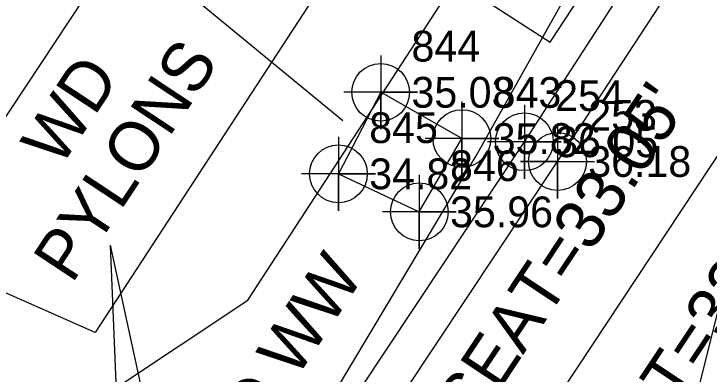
# Model space of a CAD drawing. Extents: x 2603627 to 2605187, y 896619 to 899063.
# Drawn here: x 2604536.5 to 2604593, y 898218.4 to 898247.7 of the extents above; entities that cross this region are included whole.
import ezdxf

# ---------------------------------------------------------------- set-up
doc = ezdxf.new("R2010")
doc.units = 0
for name, color, linetype in [('Exist Guardrail', 7, 'Continuous'), ('Exist Horizontal Alignment', 7, 'Continuous'), ('Exist Other Culture Area Outline', 7, 'Continuous'), ('Exist Other Culture Area Outline Cogo Elevation', 7, 'Continuous'), ('Exist Other Culture Area Outline Cogo Number', 7, 'Continuous'), ('Exist Other Culture Area Outline Cogo Point CELL', 7, 'Continuous'), ('Exist Other Culture Area Outline Leader', 7, 'Continuous'), ('Exist Other Culture Located Object Leader', 7, 'Continuous'), ('Exist Other Culture Located Object Text', 7, 'Continuous'), ('Exist Property Tie Line', 7, 'Continuous'), ('Exist Right of Way Line', 7, 'Continuous'), ('Exist Roads EOP', 7, 'Continuous'), ('Exist Roads EOP Cogo Elevation', 7, 'Continuous'), ('Exist Roads EOP Cogo Number', 7, 'Continuous'), ('Exist Roads EOP Cogo Point CELL', 7, 'Continuous'), ('Exist Roads EOT', 7, 'Continuous'), ('Exist Roads EOT Cogo Elevation', 7, 'Continuous'), ('Exist Roads EOT Cogo Number', 7, 'Continuous'), ('Exist Roads EOT Cogo Point CELL', 7, 'Continuous'), ('Exist Structure Major Bridge Seat Top Elevation', 7, 'Continuous'), ('Exist Structure Major Bridge WW Text', 7, 'Continuous'), ('Exist Utilities Telephone UG Cable SUE LOS C', 7, 'Continuous'), ('Exist Utilities Telephone UG FO SUE LOS C', 7, 'Continuous'), ('Exist Vegetation Woods Line', 7, 'Continuous')]:
    doc.layers.add(name, color=color, linetype=linetype)

# ---------------------------------------------------------------- blocks, each defined once
blk = doc.blocks.new('EXIST ROADS EOT COGO POINT')
at = {"layer": 'Exist Roads EOT Cogo Point CELL'}
blk.add_lwpolyline([(0, 0.06), (0, -0.06), (0, 0), (-0.06, 0), (0.06, 0)], dxfattribs=at)
blk.add_circle((0, 0), 0.0469, dxfattribs=at)
blk = doc.blocks.new('EXIST ROADS EOP COGO POINT')
at = {"layer": 'Exist Roads EOP Cogo Point CELL'}
blk.add_lwpolyline([(0, 0.06), (0, -0.06), (0, 0), (0.06, 0), (-0.06, 0)], dxfattribs=at)
blk.add_circle((0, 0), 0.0469, dxfattribs=at)
blk = doc.blocks.new('EXIST OTHER CULTURE AREA OUTLINE COGO POINT')
at = {"layer": 'Exist Other Culture Area Outline Cogo Point CELL'}
blk.add_lwpolyline([(0, 0.06), (0, -0.06), (0, 0), (0.06, 0), (-0.06, 0)], dxfattribs=at)
blk.add_circle((0, 0), 0.0469, dxfattribs=at)

msp = doc.modelspace()

# ---------------------------------------------------------------- linework, layer by layer
at = {"layer": 'Exist Guardrail'}
msp.add_lwpolyline([(2604549.447, 898197.005), (2604551.688, 898200.424), (2604561.034, 898214.376), (2604574.047, 898236.144), (2604583.438, 898252.897), (2604603.34, 898290.06), (2604614.453, 898307.438), (2604661.781, 898380.221)], dxfattribs=at)
at = {"layer": 'Exist Horizontal Alignment'}
msp.add_line((2604537.349, 898151.011), (2604647.762, 898317.915), dxfattribs=at)
at = {"layer": 'Exist Other Culture Area Outline'}
msp.add_lwpolyline([(2604572.88, 898237.533), (2604566.28, 898241.293), (2604562.846, 898234.669), (2604569.416, 898231.58), (2604572.88, 898237.533)], dxfattribs=at)
at = {"layer": 'Exist Other Culture Area Outline Leader'}
msp.add_line((2604563.191, 898238.978), (2604530.317, 898266.037), dxfattribs=at)
at = {"layer": 'Exist Other Culture Located Object Leader'}
for p in [(2604548.734, 898208.603), (2604545.428, 898202.545)]:
    msp.add_line(p, (2604544.327, 898228.877), dxfattribs=at)
at = {"layer": 'Exist Property Tie Line'}
msp.add_line((2604598.893, 898244.519), (2604562.447, 898098.35), dxfattribs=at)
at = {"layer": 'Exist Right of Way Line'}
msp.add_line((2604495.648, 898178.598), (2604606.061, 898345.502), dxfattribs=at)
at = {"layer": 'Exist Roads EOP'}
msp.add_line((2604550.488, 898195.948), (2604577.958, 898237.274), dxfattribs=at)
msp.add_lwpolyline([(2604577.958, 898237.274), (2604606.454, 898281.24), (2604633.893, 898322.503), (2604662.447, 898365.468), (2604690.624, 898408.056), (2604717.287, 898448.088), (2604745.459, 898490.106), (2604773.604, 898532.604), (2604800.879, 898573.951), (2604828.345, 898615.462), (2604855.104, 898656.153), (2604883.526, 898699.093), (2604911.286, 898740.949), (2604939.376, 898783.407), (2604966.332, 898824.04), (2604993.378, 898865.275), (2605022.2, 898908.378), (2605029.463, 898919.464)], dxfattribs=at)
at = {"layer": 'Exist Roads EOT'}
msp.add_line((2604553.101, 898194.261), (2604580.649, 898235.671), dxfattribs=at)
msp.add_lwpolyline([(2604580.649, 898235.671), (2604609.227, 898279.299), (2604636.662, 898320.715), (2604665.181, 898363.913), (2604693.369, 898406.363), (2604719.945, 898446.052), (2604748.005, 898488.337), (2604776.145, 898530.838), (2604803.496, 898572.303), (2604830.948, 898613.912), (2604857.578, 898654.466), (2604886.019, 898697.378), (2604913.857, 898739.329), (2604942.027, 898781.72), (2604969.056, 898822.38), (2604996.07, 898863.439), (2605024.73, 898906.725), (2605032.001, 898917.781)], dxfattribs=at)
at = {"layer": 'Exist Utilities Telephone UG Cable SUE LOS C'}
for p, q in [((2604580.043, 898245.374), (2604795.48, 898573.628)), ((2604549.351, 898265.156), (2604580.043, 898245.374))]:
    msp.add_line(p, q, dxfattribs=at)
at = {"layer": 'Exist Utilities Telephone UG FO SUE LOS C'}
for p, q in [((2604555.472, 898224.397), (2604671.199, 898402.262)), ((2604537.888, 898212.732), (2604555.472, 898224.397))]:
    msp.add_line(p, q, dxfattribs=at)
at = {"layer": 'Exist Vegetation Woods Line'}
msp.add_lwpolyline([(2604591.896, 898412.363), (2604622.511, 898404.04), (2604578.271, 898344.622), (2604545.929, 898277.972), (2604561.248, 898249.637), (2604543.064, 898221.767), (2604504.964, 898238.629), (2604486.583, 898253.52)], dxfattribs=at)

# ---------------------------------------------------------------- block references
at = {"layer": 'Exist Other Culture Area Outline Cogo Point CELL', "xscale": 50, "yscale": 50}
for p in [(2604566.28, 898241.293), (2604572.88, 898237.533), (2604562.846, 898234.669), (2604569.416, 898231.58)]:
    msp.add_blockref('EXIST OTHER CULTURE AREA OUTLINE COGO POINT', p, dxfattribs=at)
at = {"layer": 'Exist Roads EOP Cogo Point CELL', "xscale": 50, "yscale": 50}
msp.add_blockref('EXIST ROADS EOP COGO POINT', (2604577.958, 898237.274), dxfattribs=at)
at = {"layer": 'Exist Roads EOT Cogo Point CELL', "xscale": 50, "yscale": 50}
msp.add_blockref('EXIST ROADS EOT COGO POINT', (2604580.649, 898235.671), dxfattribs=at)

# ---------------------------------------------------------------- texts
at = {"layer": 'Exist Other Culture Area Outline Cogo Elevation'}
for s, p in [('35.03', (2604568.78, 898240.043)), ('35.82', (2604575.38, 898236.283)), ('34.82', (2604565.346, 898233.419)), ('35.96', (2604571.916, 898230.33))]:
    msp.add_text(s, height=2.5, dxfattribs=at).set_placement(p)
at = {"layer": 'Exist Other Culture Area Outline Cogo Number'}
for s, p in [('844', (2604568.78, 898243.793)), ('843', (2604575.38, 898240.033)), ('845', (2604565.346, 898237.169)), ('846', (2604571.916, 898234.08))]:
    msp.add_text(s, height=2.5, dxfattribs=at).set_placement(p)
at = {"layer": 'Exist Other Culture Located Object Text'}
for s, p in [('PYLONS', (2604541.188, 898225.667)), ('WD ', (2604540.221, 898235.072))]:
    msp.add_text(s, height=4, rotation=56.4785, dxfattribs=at).set_placement(p)
at = {"layer": 'Exist Roads EOP Cogo Elevation'}
msp.add_text('36.05', height=2.5, dxfattribs=at).set_placement((2604580.459, 898236.024))
at = {"layer": 'Exist Roads EOP Cogo Number'}
msp.add_text('254', height=2.5, dxfattribs=at).set_placement((2604580.459, 898239.774))
at = {"layer": 'Exist Roads EOT Cogo Elevation'}
msp.add_text('36.18', height=2.5, dxfattribs=at).set_placement((2604583.149, 898234.421))
at = {"layer": 'Exist Roads EOT Cogo Number'}
msp.add_text('253', height=2.5, dxfattribs=at).set_placement((2604583.149, 898238.171))
at = {"layer": 'Exist Structure Major Bridge Seat Top Elevation'}
for s, p in [("BRIDGE SEAT=33.05'", (2604561.73, 898195.662)), ("BRIDGE SEAT=33.04'", (2604572.449, 898188.544))]:
    msp.add_text(s, height=4, rotation=56.4094, dxfattribs=at).set_placement(p)
at = {"layer": 'Exist Structure Major Bridge WW Text'}
msp.add_text('WD WW', height=4, rotation=56.4785, dxfattribs=at).set_placement((2604553.657, 898209.289))

doc.saveas('drawing.dxf')
